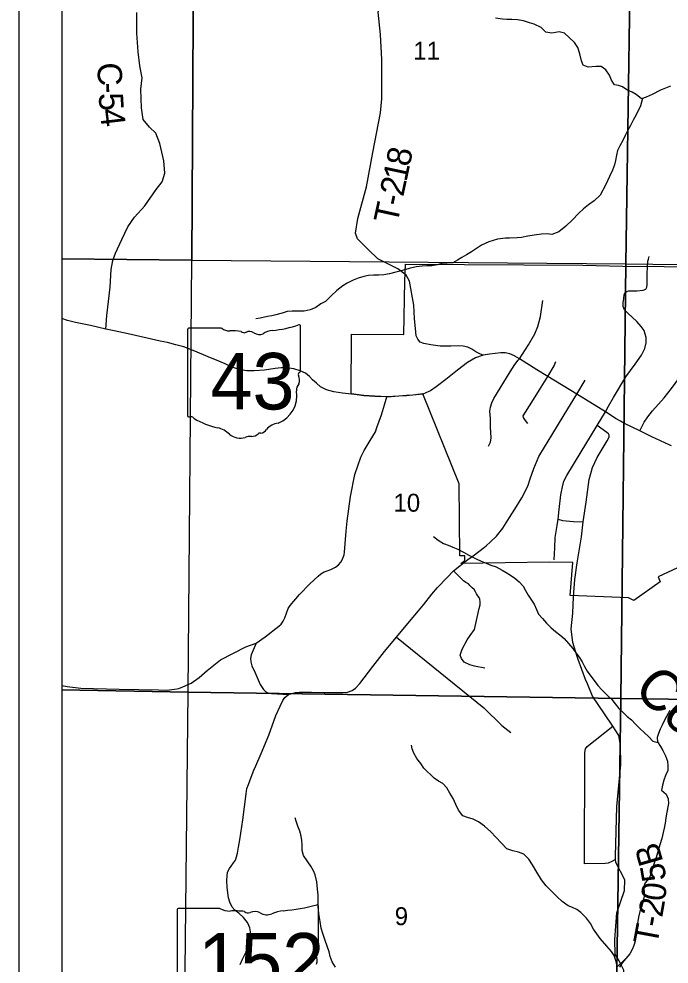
# Model space of a CAD drawing. Extents: x -19 to 40.8, y -1.8 to 26.1.
# Drawn here: x 2 to 3.517, y 18.273 to 20.478 of the extents above; entities that cross this region are included whole.
import ezdxf

# ---------------------------------------------------------------- set-up
doc = ezdxf.new("R2010")
doc.units = 0
for name, color, linetype in [('Default', 7, 'Continuous'), ('GM_X_City_Street', 7, 'Continuous'), ('GM_X_Corporation', 7, 'Continuous'), ('GM_X_County_Road_Text', 7, 'Continuous'), ('GM_X_Minor_River', 7, 'Continuous'), ('GM_X_Rail_Line', 7, 'Continuous'), ('GM_X_Rail_Line_Text', 7, 'Continuous'), ('GM_X_Section', 7, 'Continuous'), ('GM_X_Section_Text', 7, 'Continuous'), ('GM_X_State_Location', 7, 'Continuous'), ('GM_X_State_Route', 7, 'Continuous'), ('GM_X_Township_Road_Text', 7, 'Continuous'), ('GM_X_Unincorporated_Text', 7, 'Continuous'), ('RW_P_Text', 7, 'Continuous'), ('SH_Data', 7, 'Continuous')]:
    doc.layers.add(name, color=color, linetype=linetype)

msp = doc.modelspace()

# ---------------------------------------------------------------- linework, layer by layer
at = {"layer": 'Default'}
for points in [[(2.4092, 20.9), (2.1, 20.9), (2.1, 19.919), (2.4036, 19.9159)], [(3.4313, 20.9), (2.4092, 20.9), (2.4036, 19.9159), (3.4162, 19.9068)], [(4.44, 20.9), (3.4313, 20.9), (3.4162, 19.9068), (4.4251, 19.8945), (4.4266, 19.9772)], [(2.1, 19.919), (2.1, 18.9135), (2.3952, 18.9075), (2.4036, 19.9159)], [(2.1, 18.9135), (2.1, 17.9061), (2.3844, 17.899), (2.3952, 18.9075)]]:
    msp.add_lwpolyline(points, close=True, dxfattribs=at)
at = {"layer": 'GM_X_City_Street'}
msp.add_lwpolyline([(3.7171, 19.282), (3.4916, 19.1769), (3.4964, 19.1653), (3.435, 19.1215), (3.4227, 19.1277), (3.2859, 19.1336), (3.2928, 19.2104), (3.2377, 19.2109), (3.0314, 19.2081), (3.0406, 19.2151), (3.0406, 19.2255), (3.0286, 19.2255), (3.0275, 19.3938), (2.9422, 19.6035), (2.9193, 19.6009), (2.9044, 19.6), (2.8866, 19.5985), (2.8586, 19.597), (2.8303, 19.5979), (2.805, 19.6), (2.7756, 19.6039), (2.7763, 19.7426), (2.898, 19.7421), (2.9007, 19.8668), (2.9019, 19.9064), (3.3156, 19.9035), (3.4088, 19.9016), (3.6992, 19.8991)], dxfattribs=at)
at = {"layer": 'GM_X_Corporation'}
msp.add_lwpolyline([(2.2032, 19.7546), (2.2051, 19.7863), (2.2092, 19.8195), (2.2128, 19.8523), (2.2155, 19.8934), (2.2193, 19.9149), (2.2256, 19.9318), (2.2398, 19.964), (2.2544, 19.9931), (2.2701, 20.0157), (2.2942, 20.0426), (2.32, 20.08), (2.3344, 20.0982), (2.3404, 20.1188), (2.3379, 20.1472), (2.3291, 20.1877), (2.3195, 20.2118), (2.3048, 20.2259), (2.2901, 20.2438), (2.2861, 20.2707), (2.2848, 20.3143), (2.2877, 20.341), (2.2818, 20.369), (2.278, 20.4019), (2.2753, 20.4452), (2.2754, 20.4934)], dxfattribs=at)
at = {"layer": 'GM_X_Rail_Line'}
for points in [[(2.7895, 19.6015), (2.7758, 19.6033), (2.7549, 19.6051), (2.7346, 19.6084), (2.718, 19.6129), (2.704, 19.6197), (2.6947, 19.6283), (2.6852, 19.6364), (2.6778, 19.6441), (2.6685, 19.6519), (2.656, 19.6572), (2.6414, 19.6623), (2.6304, 19.6637), (2.6218, 19.6641), (2.612, 19.6641), (2.5982, 19.6626), (2.573, 19.6591), (2.5491, 19.6574), (2.5321, 19.6576), (2.5188, 19.6598), (2.5069, 19.6631), (2.4958, 19.6668), (2.481, 19.6736), (2.4664, 19.6799), (2.4417, 19.6898), (2.4108, 19.7029), (2.3847, 19.7132), (2.366, 19.7184), (2.3467, 19.7235), (2.3299, 19.7269), (2.2989, 19.7335), (2.2549, 19.7435), (2.2225, 19.7506), (2.2032, 19.7546), (2.167, 19.7628), (2.1317, 19.7704), (2.1133, 19.7748), (2.1, 19.7793)], [(3.4489, 19.5171), (3.4586, 19.5373), (3.4671, 19.5504), (3.4787, 19.5641), (3.5057, 19.5941), (3.5229, 19.6162), (3.5395, 19.6395), (3.5521, 19.6559), (3.5635, 19.6684), (3.5768, 19.68), (3.5974, 19.6951), (3.618, 19.707), (3.6387, 19.7171), (3.661, 19.7252), (3.6778, 19.7312)], [(3.1575, 19.6915), (3.1566, 19.6921), (3.1458, 19.697), (3.1345, 19.6996), (3.1246, 19.6997), (3.1112, 19.6981), (3.0977, 19.6961), (3.0835, 19.6936), (3.0654, 19.6875), (3.0467, 19.6769), (3.0234, 19.659), (2.996, 19.6372), (2.9733, 19.6203), (2.9602, 19.611), (2.9566, 19.6094)], [(3.2087, 19.66), (3.1679, 19.685), (3.1575, 19.6915)], [(3.302, 19.6027), (3.2342, 19.6444), (3.2087, 19.66)], [(2.8688, 19.597), (2.8588, 19.5965), (2.8305, 19.5974), (2.8052, 19.5994), (2.7895, 19.6015)], [(2.9566, 19.6094), (2.9424, 19.603), (2.9195, 19.6003), (2.9046, 19.5994), (2.8868, 19.598), (2.8688, 19.597)], [(3.0904, 19.2494), (3.1006, 19.2583), (3.1143, 19.2716), (3.1291, 19.2906), (3.1446, 19.3152), (3.1569, 19.3345), (3.1732, 19.361), (3.1872, 19.3884), (3.1932, 19.4057), (3.2011, 19.4296), (3.213, 19.4573), (3.226, 19.4791), (3.2435, 19.507), (3.272, 19.5545), (3.302, 19.6027)], [(3.4038, 19.5397), (3.3934, 19.5455), (3.3688, 19.5614), (3.302, 19.6027)], [(3.4489, 19.5171), (3.4133, 19.5343), (3.4038, 19.5397)], [(3.5223, 19.4822), (3.5169, 19.4846), (3.4765, 19.5036), (3.4489, 19.5171)], [(3.0598, 19.2262), (3.0867, 19.2463), (3.0904, 19.2494)], [(2.5162, 18.2726), (2.5214, 18.2851), (2.5294, 18.3005), (2.5356, 18.3133), (2.5386, 18.325), (2.5407, 18.3395), (2.5404, 18.3491), (2.5389, 18.3579), (2.5365, 18.3636), (2.5331, 18.3706), (2.524, 18.3824), (2.513, 18.3923), (2.5041, 18.3994), (2.4978, 18.4064), (2.4921, 18.4179), (2.4888, 18.4282), (2.4859, 18.4524), (2.4851, 18.4689), (2.4856, 18.4784), (2.4871, 18.4882), (2.491, 18.4962), (2.4952, 18.5022), (2.5009, 18.5097), (2.505, 18.5162), (2.5079, 18.5239), (2.5102, 18.5326), (2.5121, 18.5459), (2.5154, 18.5631), (2.5227, 18.6099), (2.5303, 18.6707), (2.5322, 18.6828), (2.5354, 18.6927), (2.5419, 18.7098), (2.5485, 18.7257), (2.5532, 18.7361), (2.5649, 18.7651), (2.5829, 18.8077), (2.5996, 18.8536), (2.6095, 18.8754), (2.6156, 18.8881), (2.6206, 18.8951), (2.6287, 18.9025), (2.6451, 18.9067), (2.6538, 18.9076), (2.6827, 18.9075), (2.7125, 18.9073), (2.7449, 18.9067), (2.756, 18.907), (2.7669, 18.9078), (2.7773, 18.9113), (2.7853, 18.9172), (2.7952, 18.9277), (2.826, 18.9674), (2.8528, 19.0023), (2.8814, 19.0362), (2.9112, 19.0724), (2.9323, 19.0977), (2.9442, 19.1118), (2.9638, 19.1363), (2.9769, 19.1518), (2.9981, 19.1748), (3.0144, 19.1905), (3.0475, 19.217), (3.0598, 19.2262)]]:
    msp.add_lwpolyline(points, dxfattribs=at)
at = {"layer": 'GM_X_Rail_Line_Text'}
msp.add_line((3.302, 19.6027), (3.3214, 19.6357), dxfattribs=at)
for points in [[(3.2486, 19.2165), (3.2501, 19.2444), (3.2514, 19.2684), (3.2559, 19.2969), (3.2584, 19.3113), (3.2602, 19.3341), (3.2647, 19.3681), (3.268, 19.3867), (3.2717, 19.3998), (3.2785, 19.413), (3.312, 19.4687), (3.334, 19.504), (3.3495, 19.5295), (3.3688, 19.5614), (3.3755, 19.5749), (3.387, 19.5951), (3.4158, 19.6432), (3.438, 19.673), (3.4524, 19.694), (3.4602, 19.7094), (3.4636, 19.7228), (3.4639, 19.7348), (3.4613, 19.7428), (3.4588, 19.7518), (3.4516, 19.7609), (3.4415, 19.7725), (3.4208, 19.792), (3.413, 19.7995), (3.4096, 19.8073), (3.4097, 19.8161), (3.4111, 19.8259), (3.4122, 19.8353), (3.4146, 19.84), (3.4185, 19.8428), (3.4225, 19.8441), (3.4418, 19.8439), (3.4568, 19.8452), (3.4629, 19.8476), (3.4655, 19.8522), (3.4657, 19.8577), (3.4657, 19.8796), (3.4664, 19.9028), (3.4671, 19.9092), (3.4676, 19.9134), (3.4687, 19.918), (3.4706, 19.9241)], [(3.0835, 19.6936), (3.0752, 19.6969), (3.0661, 19.702), (3.0565, 19.7081), (3.0473, 19.7127), (3.0369, 19.7149), (3.0257, 19.7157), (3.0075, 19.715), (2.9827, 19.7147), (2.9609, 19.7182), (2.945, 19.7211), (2.9363, 19.7245), (2.9311, 19.7314), (2.9273, 19.739), (2.9264, 19.7475), (2.9229, 19.7798), (2.9214, 19.8104), (2.911, 19.8665)], [(3.0958, 19.4817), (3.1006, 19.4909), (3.1022, 19.5007), (3.1004, 19.527), (3.1001, 19.5461), (3.0992, 19.5634), (3.1003, 19.573), (3.1033, 19.5827), (3.1084, 19.5925), (3.1463, 19.6548), (3.1571, 19.672), (3.165, 19.6821), (3.1679, 19.685), (3.1888, 19.7178), (3.2037, 19.7439), (3.2108, 19.7607), (3.2172, 19.7842), (3.2223, 19.8218)], [(3.1874, 19.5347), (3.1796, 19.5446), (3.1771, 19.5487), (3.1767, 19.5525), (3.1965, 19.5844), (3.2147, 19.6132), (3.2342, 19.6444), (3.2488, 19.6691), (3.2528, 19.6789)], [(3.3022, 19.2096), (3.313, 19.2703), (3.3168, 19.3053), (3.3236, 19.351), (3.3308, 19.4037), (3.3382, 19.4322), (3.3489, 19.4554), (3.3729, 19.4939), (3.3757, 19.4996), (3.377, 19.5034), (3.3774, 19.5072), (3.3755, 19.5105), (3.372, 19.5134), (3.3495, 19.5295)], [(3.2584, 19.3113), (3.2683, 19.3085), (3.2938, 19.3059), (3.3168, 19.3053)]]:
    msp.add_lwpolyline(points, dxfattribs=at)
at = {"layer": 'GM_X_Section'}
for points in [[(3.5203, 20.3211), (3.5086, 20.3164), (3.4972, 20.312), (3.4779, 20.3022), (3.4636, 20.2956), (3.453, 20.2916), (3.4403, 20.3017), (3.4307, 20.3077), (3.4184, 20.3128), (3.4085, 20.3195), (3.3989, 20.3232), (3.3894, 20.3242), (3.3824, 20.3355), (3.3777, 20.3469), (3.3695, 20.3597), (3.3588, 20.3672), (3.3458, 20.367), (3.328, 20.366), (3.3169, 20.3708), (3.3125, 20.3806), (3.3085, 20.3966), (3.3045, 20.4114), (3.2964, 20.4234), (3.2841, 20.435), (3.2733, 20.4452), (3.2603, 20.448), (3.2436, 20.4451), (3.2295, 20.4472), (3.2183, 20.4581), (3.2026, 20.4659), (3.1912, 20.4695), (3.1774, 20.4735), (3.1633, 20.476), (3.15, 20.4766), (3.1386, 20.4768), (3.1287, 20.4774), (3.1123, 20.4799)], [(3.4548, 20.2923), (3.4505, 20.2756), (3.4405, 20.2549), (3.4338, 20.2434), (3.4267, 20.2296), (3.42, 20.2169), (3.4148, 20.2065), (3.4089, 20.195), (3.4018, 20.182), (3.397, 20.1713), (3.3945, 20.1602), (3.3924, 20.1484), (3.3895, 20.1377), (3.3847, 20.1258), (3.378, 20.1105), (3.3691, 20.0924), (3.3561, 20.0675), (3.3422, 20.0536), (3.3294, 20.0447), (3.3177, 20.0354), (3.306, 20.0242), (3.2918, 20.0095), (3.2763, 19.9952), (3.2598, 19.9813), (3.2431, 19.9753), (3.2324, 19.9771), (3.2191, 19.9765), (3.2024, 19.974), (3.1876, 19.9715), (3.1724, 19.9686), (3.1629, 19.9677), (3.145, 19.9667), (3.1355, 19.967), (3.1165, 19.9644), (3.1063, 19.9616), (3.0961, 19.9581), (3.079, 19.9506), (3.0677, 19.9424), (3.056, 19.9346), (3.0443, 19.9276), (3.0337, 19.9218), (3.0232, 19.9152), (3.0126, 19.9093), (2.9993, 19.9087), (2.9871, 19.9074), (2.9757, 19.905), (2.9632, 19.9021), (2.9518, 19.902), (2.9408, 19.9015), (2.9267, 19.9001), (2.9104, 19.8961), (2.8948, 19.8917), (2.8797, 19.8873), (2.8649, 19.8833), (2.8516, 19.8816), (2.8398, 19.8806), (2.8273, 19.8805), (2.8155, 19.8795), (2.8045, 19.8771), (2.7916, 19.8735), (2.7798, 19.8692), (2.7662, 19.8621), (2.756, 19.8559), (2.7421, 19.845), (2.7289, 19.8323), (2.7154, 19.8195), (2.7044, 19.8133), (2.6931, 19.8055), (2.6795, 19.7996), (2.6658, 19.7964), (2.6518, 19.7962), (2.6373, 19.7964), (2.6259, 19.7955), (2.6142, 19.7919), (2.5997, 19.7879), (2.5903, 19.7858), (2.5804, 19.7842), (2.5629, 19.7805), (2.5531, 19.7788)], [(2.967, 19.2713), (2.9782, 19.262), (2.9905, 19.2549), (3.0015, 19.2509), (3.0126, 19.2461), (3.0241, 19.2416), (3.0375, 19.2346), (3.0498, 19.2275), (3.067, 19.219), (3.0785, 19.2135), (3.09, 19.2087), (3.1015, 19.2043), (3.1133, 19.1999), (3.1275, 19.1924), (3.1371, 19.1869), (3.147, 19.1809), (3.157, 19.1734), (3.1674, 19.1652), (3.1763, 19.155), (3.1817, 19.1452), (3.1884, 19.1339), (3.2023, 19.1128), (3.2078, 19.1003), (3.2125, 19.0897), (3.2218, 19.0795), (3.231, 19.069), (3.2418, 19.0581), (3.2522, 19.0495), (3.2622, 19.0417), (3.2719, 19.0327), (3.2823, 19.021), (3.2923, 19.0097), (3.2993, 18.9996), (3.307, 18.9894), (3.3144, 18.9785), (3.3199, 18.9679), (3.3257, 18.9569), (3.3346, 18.9452), (3.3424, 18.9351), (3.3509, 18.923), (3.3598, 18.9132), (3.3736, 18.8997), (3.3837, 18.8904), (3.391, 18.8802), (3.3999, 18.87), (3.4096, 18.8603), (3.4196, 18.8509), (3.4296, 18.8431), (3.4388, 18.8333), (3.4488, 18.8232), (3.4589, 18.8134), (3.4697, 18.8033), (3.4789, 18.7935), (3.4912, 18.79)], [(3.5191, 18.8652), (3.5113, 18.851), (3.5057, 18.8411), (3.5013, 18.8311), (3.4964, 18.8215), (3.4924, 18.8112), (3.4895, 18.8017), (3.49, 18.7918), (3.4973, 18.7812), (3.5028, 18.7714), (3.509, 18.7593), (3.5134, 18.7472), (3.5143, 18.7362), (3.5144, 18.7248), (3.5085, 18.7137), (3.5048, 18.7022), (3.502, 18.6911), (3.4994, 18.6789), (3.5106, 18.6696), (3.5149, 18.659), (3.5155, 18.6479), (3.5112, 18.6243), (3.5098, 18.614), (3.5081, 18.6022), (3.5056, 18.5904), (3.503, 18.5801), (3.4998, 18.5663), (3.4958, 18.5518), (3.4867, 18.522), (3.4823, 18.509), (3.4794, 18.4995), (3.4761, 18.4877), (3.4713, 18.4747), (3.4612, 18.4627), (3.4572, 18.4528), (3.4588, 18.4429), (3.4586, 18.4319), (3.4561, 18.4185), (3.4536, 18.4086), (3.4488, 18.396), (3.4455, 18.383), (3.4438, 18.3731), (3.442, 18.3617), (3.4403, 18.348), (3.4389, 18.3362), (3.4379, 18.3266), (3.435, 18.3171), (3.4313, 18.3072), (3.4254, 18.2976), (3.416, 18.2868)], [(3.416, 18.2868), (3.3957, 18.2671), (3.3936, 18.2796), (3.3889, 18.2933), (3.3827, 18.3031), (3.3715, 18.3151), (3.356, 18.3335), (3.3486, 18.344), (3.3409, 18.3553), (3.3335, 18.3678), (3.3246, 18.3806), (3.3115, 18.3937), (3.3019, 18.4008), (3.2919, 18.4053), (3.2816, 18.4093), (3.2677, 18.4194), (3.2562, 18.4306), (3.2431, 18.4426), (3.2303, 18.4557), (3.2191, 18.47), (3.2082, 18.4878), (3.1981, 18.5051), (3.1896, 18.5183), (3.1784, 18.5296), (3.1658, 18.5347), (3.1528, 18.5376), (3.1386, 18.5423), (3.1259, 18.5555), (3.1132, 18.5698), (3.1008, 18.5821), (3.0866, 18.5953), (3.0727, 18.6057), (3.0597, 18.6116), (3.0467, 18.6153), (3.036, 18.6193), (3.0256, 18.6328), (3.0193, 18.6461), (3.0131, 18.6601), (3.0057, 18.6725), (2.9983, 18.6846), (2.989, 18.6947), (2.979, 18.6999), (2.9691, 18.707), (2.9452, 18.7303), (2.9382, 18.7412), (2.9285, 18.7529), (2.9215, 18.7653), (2.9175, 18.7759), (2.9159, 18.7839)], [(2.7386, 18.2661), (2.7312, 18.2785), (2.7265, 18.2914), (2.7237, 18.3024), (2.7146, 18.3285), (2.709, 18.3448), (2.7054, 18.3576), (2.7026, 18.3732), (2.6997, 18.3918), (2.6983, 18.4081), (2.698, 18.434), (2.697, 18.4484), (2.6953, 18.4655), (2.6912, 18.4814), (2.6873, 18.4913), (2.6811, 18.5019), (2.6745, 18.512), (2.664, 18.5267), (2.6608, 18.5381), (2.6606, 18.5522), (2.6601, 18.562), (2.6588, 18.5715), (2.6553, 18.5833), (2.6509, 18.5954), (2.6466, 18.6071), (2.6446, 18.6147)], [(3.416, 18.2868), (3.4078, 18.2764), (3.401, 18.2664)]]:
    msp.add_lwpolyline(points, dxfattribs=at)
at = {"layer": 'GM_X_State_Route'}
for points in [[(4.3921, 17.8104), (4.3932, 17.8891), (4.4038, 18.6476), (4.4141, 19.3749), (4.4289, 20.4268), (4.4356, 20.9), (2.1, 20.9), (2.1, 15.8991), (2.1833, 15.8974), (3.0926, 15.8861), (3.7032, 15.8784), (3.9893, 15.872), (4.3628, 15.868), (4.3644, 15.9666), (4.3704, 16.384), (4.3769, 16.7589)], [(2.911, 19.8665), (2.9036, 19.8809), (2.884, 19.8957), (2.8377, 19.9185), (2.8158, 19.9395), (2.7904, 19.9651), (2.7852, 19.9789), (2.7911, 20.0128), (2.8109, 20.0866), (2.8259, 20.1664), (2.8435, 20.2596), (2.8469, 20.2921), (2.8471, 20.3839), (2.8435, 20.4418), (2.8384, 20.4944), (2.8483, 20.5276), (2.8631, 20.5781), (2.8794, 20.6318), (2.8933, 20.674), (2.8983, 20.7432), (2.9267, 20.823), (2.9517, 20.9)], [(2.1, 18.9236), (2.1129, 18.9208), (2.1444, 18.9173), (2.2343, 18.9147), (2.326, 18.9129), (2.3452, 18.9122), (2.3628, 18.9151), (2.3732, 18.9165), (2.3824, 18.9201), (2.4017, 18.9288), (2.4205, 18.942), (2.4392, 18.958), (2.47, 18.9831), (2.5297, 19.0132), (2.5538, 19.0221), (2.5745, 19.0371), (2.6064, 19.0617), (2.6119, 19.0666), (2.6167, 19.0733), (2.6204, 19.0812), (2.6279, 19.1029), (2.633, 19.1097), (2.6551, 19.1354), (2.679, 19.1604), (2.6979, 19.1783), (2.7046, 19.1839), (2.7121, 19.1882), (2.7194, 19.1911), (2.7277, 19.194), (2.7385, 19.1995), (2.7454, 19.2048), (2.7508, 19.2111), (2.7548, 19.2178), (2.7571, 19.2242), (2.7586, 19.2283), (2.7594, 19.2344), (2.7634, 19.2837), (2.7656, 19.3068), (2.7736, 19.3644), (2.7841, 19.4155), (2.7979, 19.4559), (2.8058, 19.4718), (2.8198, 19.4952), (2.8318, 19.5153), (2.835, 19.5253), (2.8463, 19.5548), (2.8528, 19.5777), (2.8588, 19.5965)], [(3.3053, 18.984), (3.3028, 18.991), (3.2922, 19.0237), (3.2883, 19.0558), (3.2927, 19.0918), (3.2941, 19.1304), (3.2975, 19.1703), (3.3022, 19.2096)], [(3.0873, 18.9638), (3.0631, 18.9688), (3.0518, 18.9719), (3.0392, 18.9779), (3.0327, 18.9862), (3.0298, 18.9939), (3.0345, 19.0078), (3.0458, 19.0296), (3.0532, 19.0403), (3.0627, 19.054), (3.0743, 19.1028), (3.0759, 19.1112), (3.0761, 19.1188), (3.0754, 19.1249), (3.0739, 19.129), (3.0707, 19.1327), (3.0679, 19.1374), (3.0657, 19.1415), (3.0622, 19.1472), (3.0576, 19.1512), (3.0531, 19.1559), (3.0489, 19.1607), (3.0432, 19.1636), (3.037, 19.1677), (3.0144, 19.1905)], [(2.8814, 19.0362), (3.0849, 18.8715), (3.1268, 18.8298), (3.1477, 18.8134)], [(2.5538, 19.0221), (2.5423, 18.9949), (2.5403, 18.9862), (2.541, 18.9787), (2.5438, 18.9694), (2.5513, 18.9527), (2.5626, 18.9255), (2.571, 18.9137), (2.5754, 18.9092), (2.581, 18.9059), (2.589, 18.9045), (2.6287, 18.9025)], [(3.3266, 18.927), (3.3223, 18.9376), (3.3053, 18.984)], [(3.3436, 18.0632), (3.3751, 18.1424), (3.3925, 18.1811), (3.4091, 18.2186), (3.4113, 18.2596), (3.4006, 18.281), (3.3912, 18.2956), (3.3908, 18.3305), (3.3952, 18.3929), (3.413, 18.4449), (3.414, 18.4703), (3.393, 18.5105), (3.3918, 18.5178), (3.392, 18.5252), (3.3952, 18.6407), (3.4045, 18.7387), (3.4036, 18.7837), (3.3997, 18.8066), (3.3858, 18.8281), (3.3665, 18.8574), (3.338, 18.8988), (3.3266, 18.927)], [(3.3918, 18.5178), (3.3816, 18.5118), (3.3753, 18.5092), (3.3677, 18.5084), (3.3198, 18.5076), (3.3203, 18.7672), (3.3221, 18.7758), (3.3262, 18.781), (3.3858, 18.8281)]]:
    msp.add_lwpolyline(points, dxfattribs=at)
at = {"layer": 'GM_X_Unincorporated_Text'}
for p, q in [((2.4731, 19.7567), (2.3959, 19.7567)), ((2.6569, 19.657), (2.6569, 19.7617)), ((2.3933, 19.7533), (2.3933, 19.5532)), ((2.6569, 19.657), (2.6569, 19.657)), ((2.3694, 18.4), (2.3694, 18.1998)), ((2.4691, 18.4034), (2.3726, 18.4034)), ((2.699, 18.3037), (2.699, 18.4084)), ((2.6989, 18.3037), (2.699, 18.3037))]:
    msp.add_line(p, q, dxfattribs=at)
for centre, radius, start, end in [((2.3963, 19.7537), 0.00305, 98.1301, 188.1301), ((2.4915, 19.78), 0.0296, 231.6195, 271.1119), ((2.563, 20.0296), 0.2796, 275.8445, 288.9065), ((2.654, 19.7621), 0.00294, 351.8621, 97.738), ((2.5013, 19.6444), 0.1064, 80.4867, 94.9883), ((2.5254, 19.7548), 0.00855, 219.7921, 297.1024), ((2.538, 19.7316), 0.0178, 54.4667, 119.1411), ((2.5609, 19.7634), 0.0214, 233.8562, 294.8282), ((2.5987, 19.6956), 0.0563, 97.3462, 120.7689), ((2.6563, 19.6493), 0.00454, 107.944, 210.337), ((2.6274, 19.6361), 0.0273, 340.033, 23.6496), ((2.6538, 19.6566), 0.00314, 289.6038, 7.7341), ((2.6675, 19.6132), 0.0198, 136.8065, 186.9296), ((2.5787, 19.5999), 0.0699, 292.3089, 8.9858), ((2.3963, 19.5527), 0.00308, 171.9584, 258.3066), ((2.3968, 19.5732), 0.0235, 267.339, 280.6039), ((2.4016, 19.5416), 0.00848, 29.7484, 93.2717), ((2.5087, 19.7214), 0.2019, 240.4129, 257.1985), ((2.4485, 19.4633), 0.0632, 47.1842, 75.836), ((2.5596, 19.5338), 0.0226, 282.8732, 323.2771), ((2.6082, 19.497), 0.0383, 94.4031, 142.5768), ((2.5168, 19.5406), 0.0401, 230.7004, 286.2918), ((2.54, 19.4714), 0.0329, 85.6951, 111.2099), ((2.5429, 19.5257), 0.0214, 268.777, 315.5493), ((2.5622, 19.5063), 0.00601, 65.7517, 132.6484)]:
    msp.add_arc(centre, radius, start, end, dxfattribs=at)
for centre, major_axis, start_param, end_param in [((2.5816, 18.6762), (0.3495, 0), 4.814394, 5.042369), ((2.6953, 18.4088), (0.00367, 0), 6.141152, 7.989035), ((2.3732, 18.4004), (0.00382, 0), 1.712693, 3.28349), ((2.4921, 18.4266), (0.037, 0), 4.042523, 4.731795), ((2.5044, 18.2911), (0.133, 0), 1.404758, 1.657858), ((2.5346, 18.4014), (0.0107, 0), 3.836095, 5.185415), ((2.5503, 18.3783), (0.0222, 0), 0.950623, 2.079405), ((2.579, 18.41), (0.0267, 0), 4.081561, 5.145723), ((2.6261, 18.3423), (0.0703, 0), 1.699011, 2.107814), ((2.6951, 18.3033), (0.00393, 0), 5.05454, 6.418171), ((2.6981, 18.296), (0.00568, 0), 1.883978, 3.671073), ((2.662, 18.2828), (0.0341, 0), 5.934695, 6.695948)]:
    msp.add_ellipse(centre, major_axis=major_axis, ratio=0.8, start_param=start_param, end_param=end_param, dxfattribs=at)
at = {"layer": 'RW_P_Text'}
for points in [[(2.4036, 19.9159), (3.4162, 19.9068), (3.4048, 18.893), (2.3952, 18.9075)], [(4.4251, 19.8945), (4.411, 18.9653), (4.4081, 18.8788), (3.4048, 18.893), (3.4162, 19.9068)], [(3.4048, 18.893), (3.3895, 17.8864), (2.3844, 17.899), (2.3952, 18.9075)], [(3.4048, 18.893), (4.4081, 18.8788), (4.397, 17.9674), (4.395, 17.8752), (3.3895, 17.8864)]]:
    msp.add_lwpolyline(points, close=True, dxfattribs=at)
at = {"layer": 'SH_Data'}
for p, q in [((2, 21), (2, 14)), ((2.1, 20.9), (2.1, 14.1))]:
    msp.add_line(p, q, dxfattribs=at)

# ---------------------------------------------------------------- texts
at = {"layer": 'GM_X_County_Road_Text'}
for s, rotation, p in [('C', 272.5886, (2.1826, 20.3755)), ('-', 272.7603, (2.1847, 20.3287)), ('5', 273.4297, (2.1859, 20.3046)), ('4', 276.7221, (2.1883, 20.2661))]:
    msp.add_text(s, height=0.0568, rotation=rotation, dxfattribs=at).set_placement(p)
at = {"layer": 'GM_X_Minor_River'}
msp.add_text('Ce', height=0.09472, rotation=316.9415, dxfattribs=at).set_placement((3.4308, 18.9101))
at = {"layer": 'GM_X_Section_Text'}
for s, height, p in [('11', 0.04186, (2.9203, 20.3834)), ('10', 0.04186, (2.874, 19.3288)), ('9', 0.0419, (2.8769, 18.3643))]:
    msp.add_text(s, height=height, rotation=0, dxfattribs=at).set_placement(p)
at = {"layer": 'GM_X_State_Location'}
msp.add_text('43', height=0.000189, rotation=0, dxfattribs=at).set_placement((2.4744, 19.6262))
for s, p in [('s', (2.5221, 19.6399)), ('r', (2.5221, 19.6399)), ('r', (2.5305, 18.2866)), ('s', (2.5305, 18.2866))]:
    msp.add_text(s, height=0.000189, dxfattribs=at).set_placement(p)
at = {"layer": 'GM_X_Township_Road_Text'}
for s, rotation, p in [('8', 78.9824, (2.9117, 20.1318)), ('1', 78.0206, (2.9042, 20.0965)), ('2', 77.7701, (2.8967, 20.062)), ('-', 77.7048, (2.8918, 20.0392)), ('T', 77.6915, (2.8827, 19.9976)), ('B', 106.0988, (3.5039, 18.5123)), ('5', 99.5339, (3.5112, 18.4709)), ('0', 83.0426, (3.5074, 18.4184)), ('2', 80.2499, (3.501, 18.3809)), ('T', 79.4491, (3.4889, 18.3153)), ('-', 79.6094, (3.4967, 18.3572))]:
    msp.add_text(s, height=0.0568, rotation=rotation, dxfattribs=at).set_placement(p)
at = {"layer": 'GM_X_Unincorporated_Text'}
for s, p in [('43', (2.4469, 19.5673)), ('152', (2.4184, 18.214))]:
    msp.add_text(s, height=0.13184, dxfattribs=at).set_placement(p)

doc.saveas('drawing.dxf')
